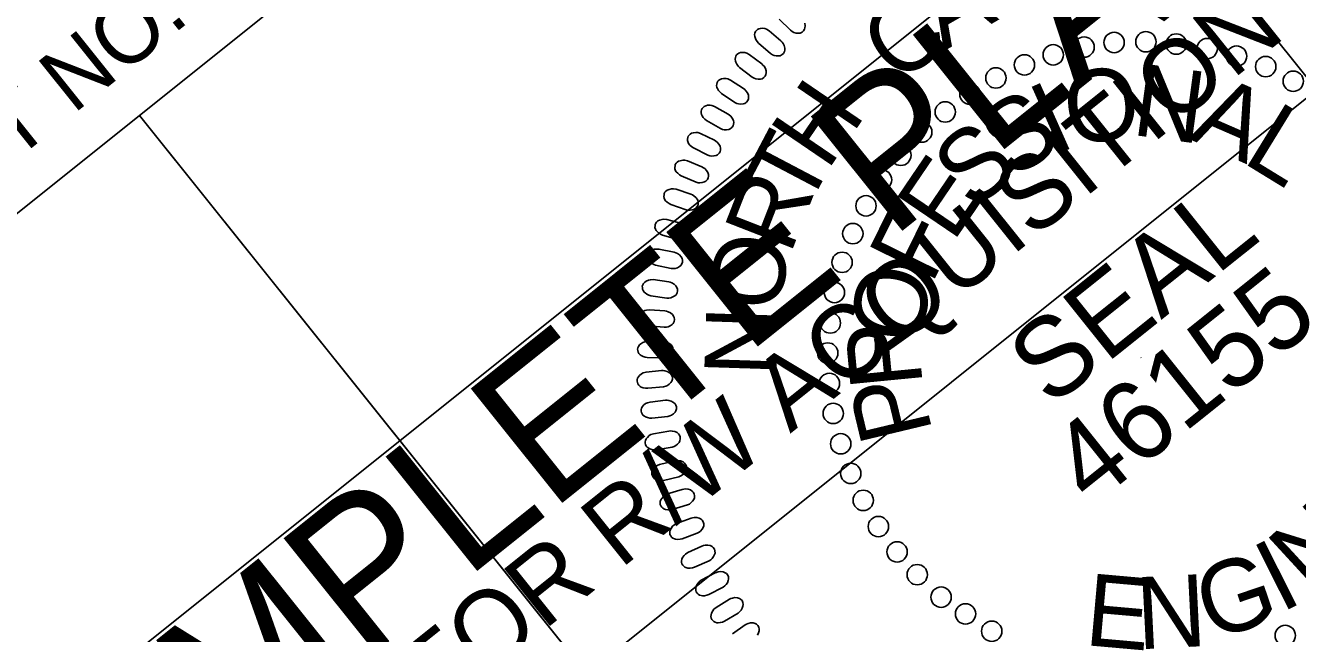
# Model space of a CAD drawing. Extents: x 472510 to 474509, y 505091 to 506998.
# Drawn here: x 473761.9 to 473861.9, y 506837.4 to 506885.2 of the extents above; entities that cross this region are included whole.
import ezdxf

# ---------------------------------------------------------------- set-up
doc = ezdxf.new("R2010")
doc.units = 0
for name, color, linetype in [('Sheet PE Seal Cell', 7, 'Continuous'), ('Sheet Plan CELL', 7, 'Continuous'), ('Sheet Sticker Incomplete CELL', 7, 'Continuous')]:
    doc.layers.add(name, color=color, linetype=linetype)

msp = doc.modelspace()

# ---------------------------------------------------------------- linework, layer by layer
at = {"layer": 'Sheet PE Seal Cell'}
msp.add_line((473849.543, 506859.097), (473849.572, 506859.06), dxfattribs=at)
for points in [[(473821.262, 506883.989), (473820.331, 506884.786), (473820.139, 506884.901), (473819.999, 506884.952), (473819.797, 506884.977), (473819.651, 506884.974), (473819.517, 506884.941), (473819.419, 506884.887), (473819.331, 506884.815), (473819.273, 506884.717), (473819.218, 506884.607), (473819.195, 506884.488), (473819.203, 506884.343), (473819.225, 506884.246), (473819.295, 506884.098), (473819.392, 506883.936), (473819.499, 506883.815), (473820.449, 506882.993), (473820.593, 506882.899), (473820.728, 506882.843), (473820.907, 506882.807), (473821.087, 506882.802), (473821.21, 506882.824), (473821.358, 506882.904), (473821.47, 506883.005), (473821.537, 506883.144), (473821.567, 506883.256), (473821.574, 506883.418), (473821.523, 506883.619), (473821.43, 506883.786), (473821.351, 506883.893)], [(473819.757, 506882.18), (473818.777, 506882.917), (473818.579, 506883.019), (473818.436, 506883.062), (473818.233, 506883.074), (473818.087, 506883.062), (473817.956, 506883.02), (473817.861, 506882.961), (473817.778, 506882.883), (473817.726, 506882.782), (473817.679, 506882.668), (473817.663, 506882.548), (473817.68, 506882.405), (473817.708, 506882.309), (473817.787, 506882.165), (473817.895, 506882.01), (473818.008, 506881.896), (473819.008, 506881.135), (473819.157, 506881.05), (473819.296, 506881.003), (473819.477, 506880.978), (473819.656, 506880.984), (473819.778, 506881.014), (473819.921, 506881.103), (473820.027, 506881.211), (473820.085, 506881.354), (473820.108, 506881.468), (473820.104, 506881.629), (473820.04, 506881.827), (473819.937, 506881.989), (473819.852, 506882.09)], [(473818.323, 506880.237), (473817.298, 506880.911), (473817.095, 506881.001), (473816.95, 506881.034), (473816.746, 506881.034), (473816.601, 506881.013), (473816.473, 506880.963), (473816.382, 506880.898), (473816.304, 506880.815), (473816.258, 506880.71), (473816.218, 506880.594), (473816.21, 506880.474), (473816.236, 506880.332), (473816.27, 506880.237), (473816.358, 506880.099), (473816.475, 506879.95), (473816.596, 506879.844), (473817.641, 506879.147), (473817.795, 506879.073), (473817.937, 506879.033), (473818.119, 506879.02), (473818.297, 506879.037), (473818.417, 506879.075), (473818.554, 506879.173), (473818.653, 506879.287), (473818.702, 506879.434), (473818.717, 506879.549), (473818.704, 506879.709), (473818.628, 506879.903), (473818.515, 506880.057), (473818.423, 506880.154)], [(473817.115, 506878.225), (473816.05, 506878.833), (473815.841, 506878.91), (473815.694, 506878.934), (473815.491, 506878.921), (473815.347, 506878.891), (473815.223, 506878.833), (473815.136, 506878.762), (473815.063, 506878.674), (473815.025, 506878.567), (473814.991, 506878.448), (473814.991, 506878.328), (473815.026, 506878.187), (473815.066, 506878.096), (473815.162, 506877.963), (473815.289, 506877.822), (473815.415, 506877.724), (473816.503, 506877.094), (473816.661, 506877.029), (473816.805, 506876.999), (473816.988, 506876.997), (473817.165, 506877.025), (473817.282, 506877.07), (473817.412, 506877.177), (473817.504, 506877.297), (473817.543, 506877.446), (473817.552, 506877.562), (473817.528, 506877.722), (473817.441, 506877.91), (473817.318, 506878.057), (473817.22, 506878.148)], [(473816.045, 506876.173), (473814.944, 506876.714), (473814.731, 506876.777), (473814.582, 506876.792), (473814.38, 506876.766), (473814.239, 506876.727), (473814.118, 506876.661), (473814.036, 506876.585), (473813.969, 506876.493), (473813.937, 506876.384), (473813.911, 506876.263), (473813.919, 506876.143), (473813.962, 506876.005), (473814.008, 506875.916), (473814.112, 506875.79), (473814.247, 506875.657), (473814.38, 506875.566), (473815.505, 506875.007), (473815.667, 506874.951), (473815.812, 506874.93), (473815.995, 506874.941), (473816.17, 506874.98), (473816.284, 506875.032), (473816.407, 506875.146), (473816.491, 506875.272), (473816.521, 506875.424), (473816.522, 506875.539), (473816.489, 506875.697), (473816.39, 506875.879), (473816.258, 506876.019), (473816.155, 506876.103)], [(473815.052, 506874.08), (473813.919, 506874.55), (473813.702, 506874.6), (473813.553, 506874.606), (473813.353, 506874.567), (473813.215, 506874.519), (473813.098, 506874.447), (473813.022, 506874.365), (473812.96, 506874.269), (473812.935, 506874.158), (473812.917, 506874.036), (473812.932, 506873.916), (473812.984, 506873.781), (473813.035, 506873.696), (473813.147, 506873.576), (473813.29, 506873.452), (473813.429, 506873.37), (473814.587, 506872.881), (473814.751, 506872.837), (473814.898, 506872.825), (473815.079, 506872.847), (473815.252, 506872.897), (473815.362, 506872.956), (473815.478, 506873.078), (473815.553, 506873.208), (473815.574, 506873.361), (473815.568, 506873.477), (473815.525, 506873.633), (473815.414, 506873.808), (473815.274, 506873.94), (473815.166, 506874.017)], [(473814.191, 506871.928), (473813.03, 506872.326), (473812.81, 506872.362), (473812.662, 506872.358), (473812.465, 506872.308), (473812.33, 506872.251), (473812.218, 506872.171), (473812.146, 506872.085), (473812.091, 506871.985), (473812.073, 506871.872), (473812.063, 506871.75), (473812.085, 506871.632), (473812.145, 506871.5), (473812.201, 506871.417), (473812.321, 506871.305), (473812.472, 506871.191), (473812.615, 506871.117), (473813.802, 506870.702), (473813.969, 506870.668), (473814.116, 506870.665), (473814.296, 506870.699), (473814.464, 506870.759), (473814.571, 506870.825), (473814.679, 506870.954), (473814.746, 506871.089), (473814.757, 506871.244), (473814.744, 506871.359), (473814.691, 506871.511), (473814.569, 506871.679), (473814.421, 506871.801), (473814.309, 506871.872)], [(473813.475, 506869.62), (473812.292, 506869.945), (473812.07, 506869.967), (473811.922, 506869.954), (473811.728, 506869.89), (473811.597, 506869.825), (473811.491, 506869.738), (473811.424, 506869.648), (473811.376, 506869.545), (473811.365, 506869.432), (473811.362, 506869.309), (473811.392, 506869.192), (473811.461, 506869.065), (473811.522, 506868.986), (473811.649, 506868.881), (473811.806, 506868.776), (473811.954, 506868.712), (473813.163, 506868.372), (473813.333, 506868.349), (473813.48, 506868.355), (473813.657, 506868.399), (473813.821, 506868.471), (473813.924, 506868.543), (473814.023, 506868.679), (473814.082, 506868.818), (473814.083, 506868.973), (473814.063, 506869.086), (473814, 506869.236), (473813.868, 506869.396), (473813.713, 506869.508), (473813.596, 506869.572)], [(473812.875, 506867.361), (473811.673, 506867.61), (473811.452, 506867.618), (473811.304, 506867.596), (473811.115, 506867.521), (473810.988, 506867.448), (473810.887, 506867.354), (473810.827, 506867.26), (473810.785, 506867.154), (473810.781, 506867.04), (473810.786, 506866.917), (473810.823, 506866.802), (473810.9, 506866.679), (473810.965, 506866.605), (473811.099, 506866.508), (473811.262, 506866.413), (473811.414, 506866.358), (473812.642, 506866.095), (473812.813, 506866.083), (473812.959, 506866.099), (473813.133, 506866.154), (473813.292, 506866.235), (473813.391, 506866.314), (473813.481, 506866.456), (473813.531, 506866.598), (473813.522, 506866.753), (473813.495, 506866.865), (473813.423, 506867.01), (473813.281, 506867.161), (473813.119, 506867.263), (473812.998, 506867.319)], [(473812.441, 506865.042), (473811.226, 506865.216), (473811.004, 506865.21), (473810.858, 506865.178), (473810.674, 506865.091), (473810.552, 506865.011), (473810.457, 506864.911), (473810.403, 506864.813), (473810.367, 506864.705), (473810.371, 506864.591), (473810.384, 506864.468), (473810.428, 506864.356), (473810.512, 506864.238), (473810.582, 506864.168), (473810.721, 506864.08), (473810.89, 506863.996), (473811.044, 506863.951), (473812.288, 506863.765), (473812.459, 506863.763), (473812.603, 506863.788), (473812.774, 506863.854), (473812.929, 506863.946), (473813.021, 506864.03), (473813.103, 506864.177), (473813.143, 506864.323), (473813.125, 506864.476), (473813.091, 506864.587), (473813.01, 506864.727), (473812.86, 506864.869), (473812.691, 506864.961), (473812.567, 506865.009)], [(473812.148, 506862.747), (473810.926, 506862.844), (473810.704, 506862.824), (473810.561, 506862.783), (473810.382, 506862.685), (473810.265, 506862.597), (473810.177, 506862.491), (473810.129, 506862.39), (473810.1, 506862.28), (473810.111, 506862.167), (473810.132, 506862.045), (473810.183, 506861.936), (473810.274, 506861.824), (473810.349, 506861.758), (473810.492, 506861.678), (473810.667, 506861.605), (473810.824, 506861.569), (473812.076, 506861.463), (473812.247, 506861.472), (473812.39, 506861.505), (473812.556, 506861.582), (473812.704, 506861.683), (473812.791, 506861.773), (473812.863, 506861.925), (473812.895, 506862.073), (473812.867, 506862.225), (473812.826, 506862.333), (473812.736, 506862.468), (473812.577, 506862.601), (473812.403, 506862.682), (473812.277, 506862.722)], [(473812.005, 506860.344), (473810.779, 506860.364), (473810.559, 506860.33), (473810.418, 506860.281), (473810.247, 506860.171), (473810.136, 506860.076), (473810.054, 506859.965), (473810.013, 506859.861), (473809.991, 506859.749), (473810.009, 506859.637), (473810.037, 506859.517), (473810.094, 506859.411), (473810.193, 506859.305), (473810.271, 506859.244), (473810.42, 506859.174), (473810.599, 506859.111), (473810.758, 506859.086), (473812.014, 506859.058), (473812.184, 506859.077), (473812.324, 506859.12), (473812.485, 506859.207), (473812.626, 506859.317), (473812.708, 506859.413), (473812.77, 506859.569), (473812.793, 506859.717), (473812.755, 506859.868), (473812.707, 506859.973), (473812.61, 506860.102), (473812.442, 506860.224), (473812.264, 506860.295), (473812.135, 506860.326)], [(473811.878, 506858.062), (473810.658, 506857.938), (473810.444, 506857.879), (473810.31, 506857.813), (473810.153, 506857.684), (473810.053, 506857.576), (473809.986, 506857.457), (473809.957, 506857.349), (473809.948, 506857.235), (473809.979, 506857.125), (473810.021, 506857.01), (473810.091, 506856.911), (473810.201, 506856.817), (473810.286, 506856.766), (473810.442, 506856.714), (473810.627, 506856.672), (473810.787, 506856.666), (473812.038, 506856.786), (473812.205, 506856.825), (473812.339, 506856.884), (473812.489, 506856.99), (473812.616, 506857.115), (473812.686, 506857.221), (473812.729, 506857.383), (473812.734, 506857.533), (473812.679, 506857.678), (473812.619, 506857.777), (473812.507, 506857.893), (473812.327, 506857.995), (473812.141, 506858.044), (473812.009, 506858.06)], [(473812.194, 506855.724), (473810.975, 506855.59), (473810.761, 506855.529), (473810.628, 506855.463), (473810.471, 506855.333), (473810.373, 506855.224), (473810.306, 506855.104), (473810.278, 506854.995), (473810.27, 506854.881), (473810.302, 506854.772), (473810.345, 506854.657), (473810.416, 506854.559), (473810.526, 506854.466), (473810.612, 506854.415), (473810.769, 506854.364), (473810.953, 506854.325), (473811.114, 506854.32), (473812.364, 506854.449), (473812.53, 506854.49), (473812.665, 506854.55), (473812.813, 506854.656), (473812.94, 506854.783), (473813.009, 506854.888), (473813.051, 506855.051), (473813.054, 506855.202), (473812.998, 506855.346), (473812.937, 506855.445), (473812.824, 506855.56), (473812.643, 506855.66), (473812.457, 506855.708), (473812.325, 506855.724)], [(473812.457, 506853.31), (473811.248, 506853.1), (473811.039, 506853.026), (473810.91, 506852.95), (473810.762, 506852.811), (473810.671, 506852.696), (473810.611, 506852.572), (473810.59, 506852.462), (473810.589, 506852.348), (473810.629, 506852.241), (473810.678, 506852.128), (473810.755, 506852.035), (473810.871, 506851.95), (473810.96, 506851.904), (473811.119, 506851.863), (473811.306, 506851.835), (473811.467, 506851.84), (473812.706, 506852.048), (473812.87, 506852.099), (473812.999, 506852.168), (473813.141, 506852.283), (473813.26, 506852.417), (473813.322, 506852.527), (473813.354, 506852.692), (473813.347, 506852.843), (473813.283, 506852.983), (473813.216, 506853.077), (473813.096, 506853.186), (473812.909, 506853.274), (473812.72, 506853.31), (473812.587, 506853.317)], [(473812.919, 506850.959), (473811.726, 506850.673), (473811.521, 506850.586), (473811.397, 506850.503), (473811.258, 506850.354), (473811.174, 506850.234), (473811.123, 506850.107), (473811.108, 506849.995), (473811.115, 506849.882), (473811.16, 506849.777), (473811.218, 506849.668), (473811.3, 506849.58), (473811.421, 506849.502), (473811.513, 506849.462), (473811.674, 506849.431), (473811.863, 506849.415), (473812.023, 506849.43), (473813.248, 506849.715), (473813.406, 506849.777), (473813.531, 506849.853), (473813.666, 506849.977), (473813.776, 506850.119), (473813.831, 506850.231), (473813.853, 506850.398), (473813.837, 506850.548), (473813.763, 506850.684), (473813.69, 506850.775), (473813.564, 506850.875), (473813.371, 506850.952), (473813.181, 506850.975), (473813.048, 506850.974)], [(473813.509, 506848.718), (473812.337, 506848.358), (473812.138, 506848.257), (473812.019, 506848.167), (473811.89, 506848.01), (473811.814, 506847.885), (473811.771, 506847.754), (473811.764, 506847.642), (473811.777, 506847.529), (473811.829, 506847.428), (473811.893, 506847.322), (473811.98, 506847.24), (473812.106, 506847.169), (473812.2, 506847.135), (473812.363, 506847.115), (473812.552, 506847.111), (473812.711, 506847.136), (473813.915, 506847.497), (473814.07, 506847.568), (473814.191, 506847.652), (473814.317, 506847.784), (473814.417, 506847.933), (473814.465, 506848.049), (473814.477, 506848.217), (473814.452, 506848.365), (473814.37, 506848.496), (473814.291, 506848.582), (473814.159, 506848.675), (473813.962, 506848.739), (473813.77, 506848.75), (473813.637, 506848.741)], [(473814.193, 506846.461), (473813.046, 506846.028), (473812.854, 506845.916), (473812.741, 506845.818), (473812.622, 506845.653), (473812.553, 506845.523), (473812.518, 506845.39), (473812.518, 506845.279), (473812.539, 506845.166), (473812.597, 506845.069), (473812.667, 506844.967), (473812.76, 506844.891), (473812.89, 506844.827), (473812.987, 506844.8), (473813.15, 506844.789), (473813.339, 506844.797), (473813.496, 506844.832), (473814.675, 506845.268), (473814.825, 506845.349), (473814.94, 506845.441), (473815.058, 506845.581), (473815.149, 506845.735), (473815.19, 506845.854), (473815.191, 506846.022), (473815.156, 506846.169), (473815.066, 506846.295), (473814.982, 506846.374), (473814.844, 506846.459), (473814.644, 506846.511), (473814.452, 506846.51), (473814.32, 506846.493)], [(473815.053, 506844.26), (473813.934, 506843.756), (473813.75, 506843.632), (473813.643, 506843.527), (473813.535, 506843.355), (473813.475, 506843.221), (473813.448, 506843.086), (473813.455, 506842.974), (473813.483, 506842.864), (473813.546, 506842.77), (473813.624, 506842.673), (473813.721, 506842.602), (473813.855, 506842.548), (473813.952, 506842.526), (473814.117, 506842.526), (473814.304, 506842.546), (473814.459, 506842.59), (473815.608, 506843.1), (473815.753, 506843.19), (473815.862, 506843.288), (473815.97, 506843.436), (473816.052, 506843.595), (473816.085, 506843.716), (473816.075, 506843.884), (473816.032, 506844.029), (473815.934, 506844.148), (473815.845, 506844.223), (473815.702, 506844.299), (473815.499, 506844.338), (473815.307, 506844.325), (473815.177, 506844.299)], [(473816.088, 506842.148), (473815.004, 506841.575), (473814.827, 506841.439), (473814.727, 506841.328), (473814.63, 506841.149), (473814.578, 506841.012), (473814.561, 506840.876), (473814.574, 506840.765), (473814.608, 506840.656), (473814.679, 506840.567), (473814.761, 506840.475), (473814.863, 506840.41), (473815, 506840.365), (473815.099, 506840.349), (473815.262, 506840.359), (473815.449, 506840.39), (473815.6, 506840.445), (473816.716, 506841.025), (473816.855, 506841.125), (473816.957, 506841.23), (473817.056, 506841.383), (473817.127, 506841.547), (473817.152, 506841.671), (473817.132, 506841.837), (473817.08, 506841.979), (473816.974, 506842.093), (473816.881, 506842.162), (473816.734, 506842.228), (473816.528, 506842.254), (473816.338, 506842.23), (473816.209, 506842.195)], [(473817.206, 506840.078), (473816.16, 506839.438), (473815.992, 506839.292), (473815.9, 506839.175), (473815.814, 506838.99), (473815.77, 506838.85), (473815.761, 506838.713), (473815.782, 506838.603), (473815.823, 506838.497), (473815.899, 506838.412), (473815.987, 506838.325), (473816.092, 506838.267), (473816.232, 506838.23), (473816.332, 506838.221), (473816.494, 506838.241), (473816.678, 506838.284), (473816.827, 506838.348), (473817.902, 506838.997), (473818.035, 506839.105), (473818.131, 506839.216), (473818.22, 506839.375), (473818.28, 506839.544), (473818.298, 506839.669), (473818.267, 506839.834), (473818.206, 506839.973), (473818.094, 506840.079), (473817.997, 506840.142), (473817.846, 506840.199), (473817.639, 506840.212), (473817.45, 506840.176), (473817.324, 506840.133)]]:
    msp.add_lwpolyline(points, close=True, dxfattribs=at)
for points in [[(473821.121, 506885.702), (473822.017, 506884.821), (473822.154, 506884.719), (473822.286, 506884.654), (473822.463, 506884.607), (473822.641, 506884.59), (473822.766, 506884.605), (473822.918, 506884.675), (473823.037, 506884.769), (473823.112, 506884.904), (473823.149, 506885.014), (473823.166, 506885.174), (473823.128, 506885.378)], [(473819.424, 506837.267), (473819.503, 506837.432), (473819.553, 506837.604), (473819.563, 506837.729), (473819.521, 506837.892), (473819.452, 506838.026), (473819.333, 506838.125), (473819.232, 506838.182), (473819.078, 506838.229), (473818.871, 506838.23), (473818.684, 506838.182), (473818.562, 506838.131), (473818.447, 506838.07), (473817.443, 506837.365)]]:
    msp.add_lwpolyline(points, dxfattribs=at)
for centre in [(473845.088, 506883.5), (473847.451, 506883.86), (473849.951, 506883.921), (473852.339, 506883.739), (473854.765, 506883.384), (473842.668, 506882.891), (473857.078, 506882.786), (473840.399, 506882.096), (473859.367, 506881.964), (473838.16, 506881.071), (473861.532, 506880.815), (473836.12, 506879.796), (473834.18, 506878.398), (473832.333, 506876.819), (473830.685, 506874.991), (473829.168, 506873.063), (473827.949, 506871.017), (473826.915, 506868.83), (473826.069, 506866.573), (473825.466, 506864.203), (473825.143, 506861.802), (473824.938, 506859.445), (473825.069, 506857.05), (473825.375, 506854.693), (473825.96, 506852.304), (473826.75, 506849.977), (473827.733, 506847.856), (473828.921, 506845.796), (473830.392, 506843.804), (473831.978, 506842.012), (473833.85, 506840.245), (473835.772, 506838.925), (473837.831, 506837.562), (473860.905, 506837.229)]:
    msp.add_circle(centre, 0.801, dxfattribs=at)
at = {"layer": 'Sheet Plan CELL'}
msp.add_line((473770.852, 506878.127), (473841.134, 506790.33), dxfattribs=at)
for points in [[(473770.852, 506878.127), (473848.909, 506940.614), (473919.222, 506852.778), (473841.155, 506790.284)], [(473692.738, 506815.611), (473770.852, 506878.127), (473841.155, 506790.284), (473763.036, 506727.795)]]:
    msp.add_lwpolyline(points, close=True, dxfattribs=at)
at = {"layer": 'Sheet Sticker Incomplete CELL'}
msp.add_lwpolyline([(473748.615, 506788.284), (473733.931, 506806.631), (473848.7, 506898.484), (473863.384, 506880.137)], close=True, dxfattribs=at)

# ---------------------------------------------------------------- texts
at = {"layer": 'Sheet PE Seal Cell'}
for s, height, rotation, p in [('A', 5.669, 29.76954, (473834.062, 506883.175)), ('C', 5.669, 36.2589, (473830.36, 506880.479)), ('O', 5.669, 8.20107, (473843.932, 506875.721)), ('N', 5.669, 352.32147, (473848.738, 506876.616)), ('H', 5.669, 55.72697, (473824.897, 506873.693)), ('I', 5.669, 24.08066, (473842.651, 506874.915)), ('A', 5.669, 336.44188, (473853.269, 506876.296)), ('S', 5.669, 32.02046, (473839.289, 506873.034)), ('L', 5.669, 328.50208, (473857.423, 506874.504)), ('T', 5.669, 62.21633, (473823.296, 506870.606)), ('S', 5.669, 39.96025, (473836.338, 506870.542)), ('E', 5.669, 55.83985, (473834.777, 506868.064)), ('R', 5.669, 68.70569, (473821.98, 506867.096)), ('F', 5.669, 63.77965, (473833.091, 506864.744)), ('SEAL', 6.2363, 38.65259, (473842.456, 506855.081)), ('O', 5.669, 81.6844, (473821.159, 506862.56)), ('O', 5.669, 79.65924, (473832.166, 506859.984)), ('46155', 6.2363, 38.65259, (473845.671, 506847.307)), ('N', 5.669, 88.17375, (473820.892, 506857.537)), ('R', 5.669, 95.53884, (473832.419, 506856.925)), ('P', 5.669, 103.47864, (473833.203, 506853.246)), ('N', 5.669, 42.5756, (473862.991, 506840.323)), ('I', 5.669, 26.696, (473860.546, 506838.971)), ('G', 5.669, 18.7562, (473855.096, 506836.773)), ('E', 5.669, 354.93681, (473845.044, 506836.483)), ('N', 5.669, 2.87661, (473849.339, 506836.134))]:
    msp.add_text(s, height=height, rotation=rotation, dxfattribs=at).set_placement(p)
at = {"layer": 'Sheet Plan CELL'}
msp.add_text('R/W SHEET NO.', height=5.0001, rotation=38.67123, dxfattribs=at).set_placement((473735.179, 506853.804))
at = {"layer": 'Sheet Sticker Incomplete CELL'}
for s, height, p in [('INCOMPLETE PLANS', 11.52, (473748.292, 506803.011)), ('DO NOT USE FOR R/W ACQUISITION', 5.76, (473755.172, 506799.615))]:
    msp.add_text(s, height=height, rotation=38.67122, dxfattribs=at).set_placement(p)

doc.saveas('drawing.dxf')
